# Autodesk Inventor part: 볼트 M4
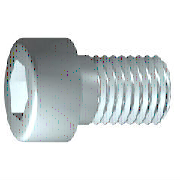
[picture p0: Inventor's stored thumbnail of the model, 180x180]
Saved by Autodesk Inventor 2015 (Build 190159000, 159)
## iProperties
IsCustomPart: 0
Created: 2012-02
Part Number: 볼트 M4
Material: 스테인리스강
Description: 6각 소켓 머리 캡 나사
Document SubType Name: Modeling
Standard: ISO 4762
Designer: mduedu
Standard Revision: Fourth edition 2004-03-01
Standards Organization: ISO
Language: ko-KR
Size Designation: M4 x 12
Categories: <MemberInstance><Categories><Category DisplayName="조임쇠" InternalName="e4da775c-781d-43d5-af7c-5136215cf5a6" Mnemonic="FSTN"><Category DisplayName="볼트" InternalN
Density: 8.08 g/cm^3
Mass: 2.29719 g
Surface Area: 3.30853 cm^2
Volume: 0.284306 cm^3
Appearance: 반광택
Author: mduedu
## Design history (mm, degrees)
sketch "스케치1"
  geometry: L1 (-1, 0)-(10, 0); L2 (10, 0)-(10, 2); L3 (10, 2)-(1.75, 2); L4 (1.75, 2)-(1.32, 2); L5 (1.32, 2)-(0, 2); L6 (0, 2)-(0, 3.5); L7 (0, 3.5)-(-4, 3.5); L8 (-4, 3.5)-(-4, 1.732); L9 (-4, 1.732)-(-2, 1.732); L10 (-2, 1.732)-(-1, 0); L11 (-7.2, 0)-(15.2, 0) reference; L12 (0, -0.7)-(0, 4.2) reference; L13 (1.75, 2)-(0, 2)
  constraints: 22 end point, 6 parallel, 2 collinear, 2 perpendicular, 1 horizontal, 1 point on line
  dimensions: "d1" = 8.25 distance from line of L3.end L2 (= GEL); "d2" = 0.42952 distance of L4.end L3.end (computed from GAL); "d3" = 4 distance between parallel lines of L8 L6 (= KOH); "d4" = 2 distance of L8.end L9.end (= INTI); "d5" = 60 deg angle of L10 L1; "d6" = 4 diameter of L3 L1 (= GD); "d7" = 4 diameter of L5 L1 (= BDM); "d8" = 3.4641 diameter of L9 L1 (= 1.1547 x SW); "d9" = 7 diameter of L7 L1 (= KOD); "d26" = 10 distance between parallel lines of L12 L2 (= NLG)
revolve "본체" sketch "스케치1" stored, may be unused: angle "d10" = 90 deg
sketch "스케치2"
  geometry: L1 (0, -4.9)-(0, 4.9) reference; L2 (-4.9, 0)-(4.9, 0) reference; L3 (1.732, 0)-(0.866, -1.5); L4 (0.866, -1.5)-(-0.866, -1.5); L5 (-0.866, -1.5)-(-1.732, 0); L6 (-1.732, 0)-(-0.866, 1.5); L7 (-0.866, 1.5)-(0.866, 1.5); L8 (0.866, 1.5)-(1.732, 0); 2 further points
  constraints: 12 end point, 1 coincident, 1 horizontal alignment, 1 point on line, 12 other
extrude "슬롯" join sketch "스케치2" stored distance "d11" = 10; taper "d12" = 0 deg
workplane "Work Plane1"
fillet "Fillet2" dims "d30" = 0.1 (= R)
body "Solid1"
fillet "모깎기1" dims "d17" = 0.4 (= RR)
feature "스레드" dims "d13" = 8.25 (= GEL), "d14" = 0
chamfer "모따기1" distance "d15" = 0.42941 (= -0.5 x SPD + 0.5 x GD); stored, may be unused: second distance "d16" = 0.42941 (= GUL), angle "d27" = 45 deg
other parameters: "GD" = 4 [user parameter; used in 2 equation terms], "NLG" = 10 [user parameter; used in 1 equation term], "GEL" = 8.25 [user parameter; used in 2 equation terms], "KOD" = 7 [user parameter; used in 1 equation term], "KOH" = 4 [user parameter; used in 1 equation term], "INTI" = 2 [user parameter; used in 1 equation term], "GAL" = 0.42941 (= 0.61345 x PTC) [user parameter; used in 1 equation term], "GUL" = 0.42941 (= 0.61345 x PTC) [user parameter; used in 1 equation term], "BDM" = 4 (= NND) [user parameter; used in 1 equation term], "SW" = 3 [user parameter; used in 2 equation terms], "RR" = 0.4 [user parameter; used in 1 equation term], "SPD" = 3.14117 (= NND - 1.2269 x PTC) [user parameter; used in 1 equation term], "d19" = 0, "d28" = 0, "d29" = 0, "R" = 0.1 [user parameter; used in 1 equation term], "TOA" = 30 deg [user parameter], "GD1" = 3.14117 (= THREADDIA - 1.2269 x PTC) [user parameter], "THREADDIA" = 4 [user parameter; used in 1 equation term], "FAWI" = 45 deg [user parameter], "TPU" = 14.28571 (computed from PTC) [user parameter], "PTC" = 0.7 [user parameter; used in 5 equation terms], "NND" = 4 [user parameter; used in 2 equation terms], "E0" = 3.465 (= 1.155 x SW) [user parameter]
